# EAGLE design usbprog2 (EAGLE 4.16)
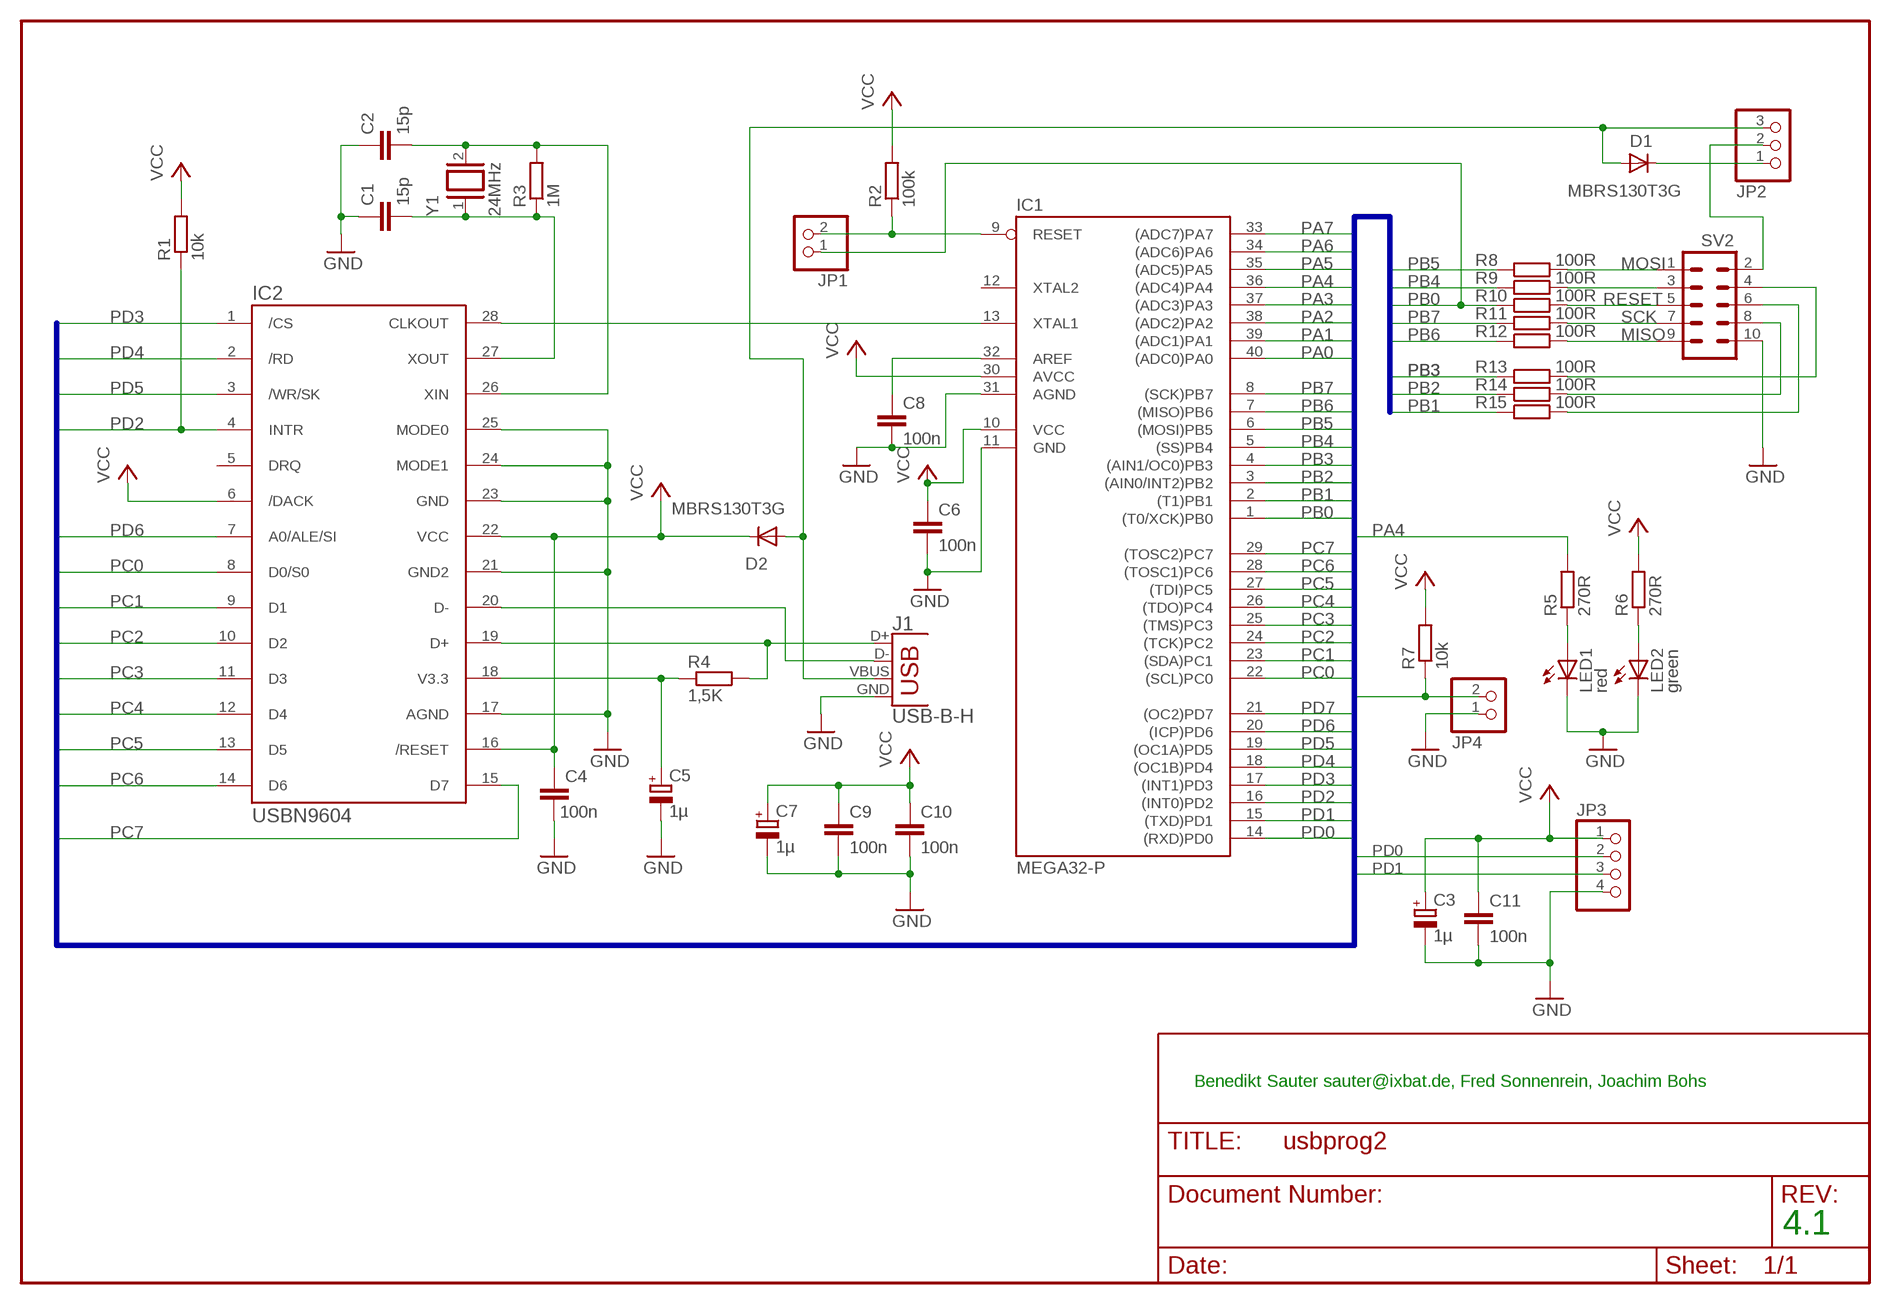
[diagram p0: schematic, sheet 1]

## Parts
C1  15p  C-EU025-024X044  [C025-024X044]
C2  15p  C-EU025-024X044  [C025-024X044]
C3  1µ  CPOL-EUE2-5  [E2-5]
C4  100n  C-EU050-024X044  [C050-024X044]
C5  1µ  CPOL-EUE2-5  [E2-5]
C6  100n  C-EU050-024X044  [C050-024X044]
C7  1µ  CPOL-EUE2-5  [E2-5]
C8  100n  C-EU050-024X044  [C050-024X044]
C9  100n  C-EU050-024X044  [C050-024X044]
C10  100n  C-EU050-024X044  [C050-024X044]
C11  100n  C-EU050-024X044  [C050-024X044]
D1  MBRS130T3G  DIODE-DO35-10  [DO35-10]
D2  MBRS130T3G  DIODE-DO35-10  [DO35-10]
IC1  MEGA32-P  [DIL40]
IC2  USBN9604  [SO28-3]
J1  USB-B-H  [USB-B-H]
JP1  PINHD-1X2  [1X02]
JP2  PINHD-1X3  [1X03]
JP3  PINHD-1X4  [1X04]
JP4  PINHD-1X2  [1X02]
LED1  red  LED3MM  [LED3MM]
LED2  green  LED3MM  [LED3MM]
R1  10k  R-EU_0207/10  [0207/10]
R2  100k  R-EU_0207/10  [0207/10]
R3  1M  R-EU_0207/10  [0207/10]
R4  1,5K  R-EU_0207/10  [0207/10]
R5  270R  R-EU_0207/10  [0207/10]
R6  270R  R-EU_0207/12  [0207/12]
R7  10k  R-EU_0207/10  [0207/10]
R8  100R  R-EU_0207/12  [0207/12]
R9  100R  R-EU_0207/12  [0207/12]
R10  100R  R-EU_0207/12  [0207/12]
R11  100R  R-EU_0207/12  [0207/12]
R12  100R  R-EU_0207/12  [0207/12]
R13  100R  R-EU_0207/12  [0207/12]
R14  100R  R-EU_0207/12  [0207/12]
R15  100R  R-EU_0207/12  [0207/12]
SV2  ML10L  [ML10L]
Y1  24MHz  XTAL/S  [QS]

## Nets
GND: C1.1 C2.1 C3.- C4.2 C5.- C6.2 C7.- C8.2 C9.2 C10.2 C11.2 IC1.11(GND) IC1.31(AGND) IC2.17(AGND) IC2.21(GND2) IC2.23(GND) IC2.24(MODE1) IC2.25(MODE0) J1.GND JP3.4 JP4.1 LED1.K(C) LED2.K(C) SV2.10
N$1: D1.A D2.A J1.VBUS JP2.3
N$2: JP2.2 SV2.2
N$3: D1.C JP2.1
N$4: IC1.13(XTAL1) IC2.28(CLKOUT)
N$5: R14.2 SV2.8
N$6: C8.1 IC1.32(AREF)
N$7: C5.+ IC2.18(V3.3) R4.1
N$8: C2.2 IC2.26(XIN) R3.2 Y1.2
N$9: LED1.A R5.1
N$10: LED2.A R6.1
N$11: C1.2 IC2.27(XOUT) R3.1 Y1.1
N$12: IC2.19(D+) J1.D+ R4.2
N$13: R15.2 SV2.6
N$14: R13.2 SV2.4
N$15: IC2.20(D-) J1.D-
N$16: R12.2 SV2.9
N$17: R11.2 SV2.7
N$18: R10.2 SV2.5
N$19: R9.2 SV2.3
N$20: R8.2 SV2.1
PA0: IC1.40((ADC0)PA0)
PA1: IC1.39((ADC1)PA1)
PA2: IC1.38((ADC2)PA2)
PA3: IC1.37((ADC3)PA3)
PA4: IC1.36((ADC4)PA4) R5.2
PA5: IC1.35((ADC5)PA5)
PA6: IC1.34((ADC6)PA6)
PA7: IC1.33((ADC7)PA7) JP4.2 R7.1
PB0: IC1.1((T0/XCK)PB0) JP1.1 R10.1
PB1: IC1.2((T1)PB1) R15.1
PB2: IC1.3((AIN0/INT2)PB2) R14.1
PB3: IC1.4((AIN1/OC0)PB3) R13.1
PB4: IC1.5((SS)PB4) R9.1
PB5: IC1.6((MOSI)PB5) R8.1
PB6: IC1.7((MISO)PB6) R12.1
PB7: IC1.8((SCK)PB7) R11.1
PC0: IC1.22((SCL)PC0) IC2.8(D0/S0)
PC1: IC1.23((SDA)PC1) IC2.9(D1)
PC2: IC1.24((TCK)PC2) IC2.10(D2)
PC3: IC1.25((TMS)PC3) IC2.11(D3)
PC4: IC1.26((TDO)PC4) IC2.12(D4)
PC5: IC1.27((TDI)PC5) IC2.13(D5)
PC6: IC1.28((TOSC1)PC6) IC2.14(D6)
PC7: IC1.29((TOSC2)PC7) IC2.15(D7)
PD0: IC1.14((RXD)PD0) JP3.2
PD1: IC1.15((TXD)PD1) JP3.3
PD2: IC1.16((INT0)PD2) IC2.4(INTR) R1.1
PD3: IC1.17((INT1)PD3) IC2.1(/CS)
PD4: IC1.18((OC1B)PD4) IC2.2(/RD)
PD5: IC1.19((OC1A)PD5) IC2.3(/WR/SK)
PD6: IC1.20((ICP)PD6) IC2.7(A0/ALE/SI)
PD7: IC1.21((OC2)PD7)
RESET: IC1.9(RESET) JP1.2 R2.1
VCC: C3.+ C4.1 C6.1 C7.+ C9.1 C10.1 C11.1 D2.C IC1.10(VCC) IC1.30(AVCC) IC2.6(/DACK) IC2.16(/RESET) IC2.22(VCC) JP3.1 R1.2 R2.2 R6.2 R7.2
Unconnected: IC1.12(XTAL2) IC2.5(DRQ)

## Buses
PD0,PD1,PD2,PD3,PD4,PD5,PD6,PD7,PC0,PC1,PC2,PC3,PC4,PC5,PC6,PC7,PB0,PB1,PB2,PB3,PB4,PB5,PB6,PB7,PA0,PA1,PA2,PA3,PA4,PA5,PA6,PA7

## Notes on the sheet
- MOSI
- PB4
- RESET
- SCK
- MISO
- PB3 | PB3
- PB2
- PB1
- Benedikt Sauter sauter@ixbat.de, Fred Sonnenrein, Joachim Bohs
- 4.1

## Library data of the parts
C1 C2 C4 C6 C8-C11 = rcl:C-EU: CAPACITOR, European symbol
C3 C5 C7 = rcl:CPOL-EU: POLARIZED CAPACITOR, European symbol
D1 D2 = diode:DIODE-: DIODE
IC1 = atmel:MEGA32-P: MICROCONTROLLER 32 Kbytes FLASH 2 Kbytes SRAM 1 Kbytes EEPROM USART 8-channel 10 bit ADC Source: www.atmel.com .. doc2503.pdf
IC2 = bene:USBN9604
J1 = con-usb:USB: USB Connectors
JP1 JP4 = pinhead:PINHD-1X2: PIN HEADER
JP2 = pinhead:PINHD-1X3: PIN HEADER
JP3 = pinhead:PINHD-1X4: PIN HEADER
LED1 LED2 = led:LED: LED
R1-R15 = rcl:R-EU_: RESISTOR, European symbol
SV2 = con-harting-ml:ML10: HARTING
Y1 = special:XTAL/S: CRYSTAL

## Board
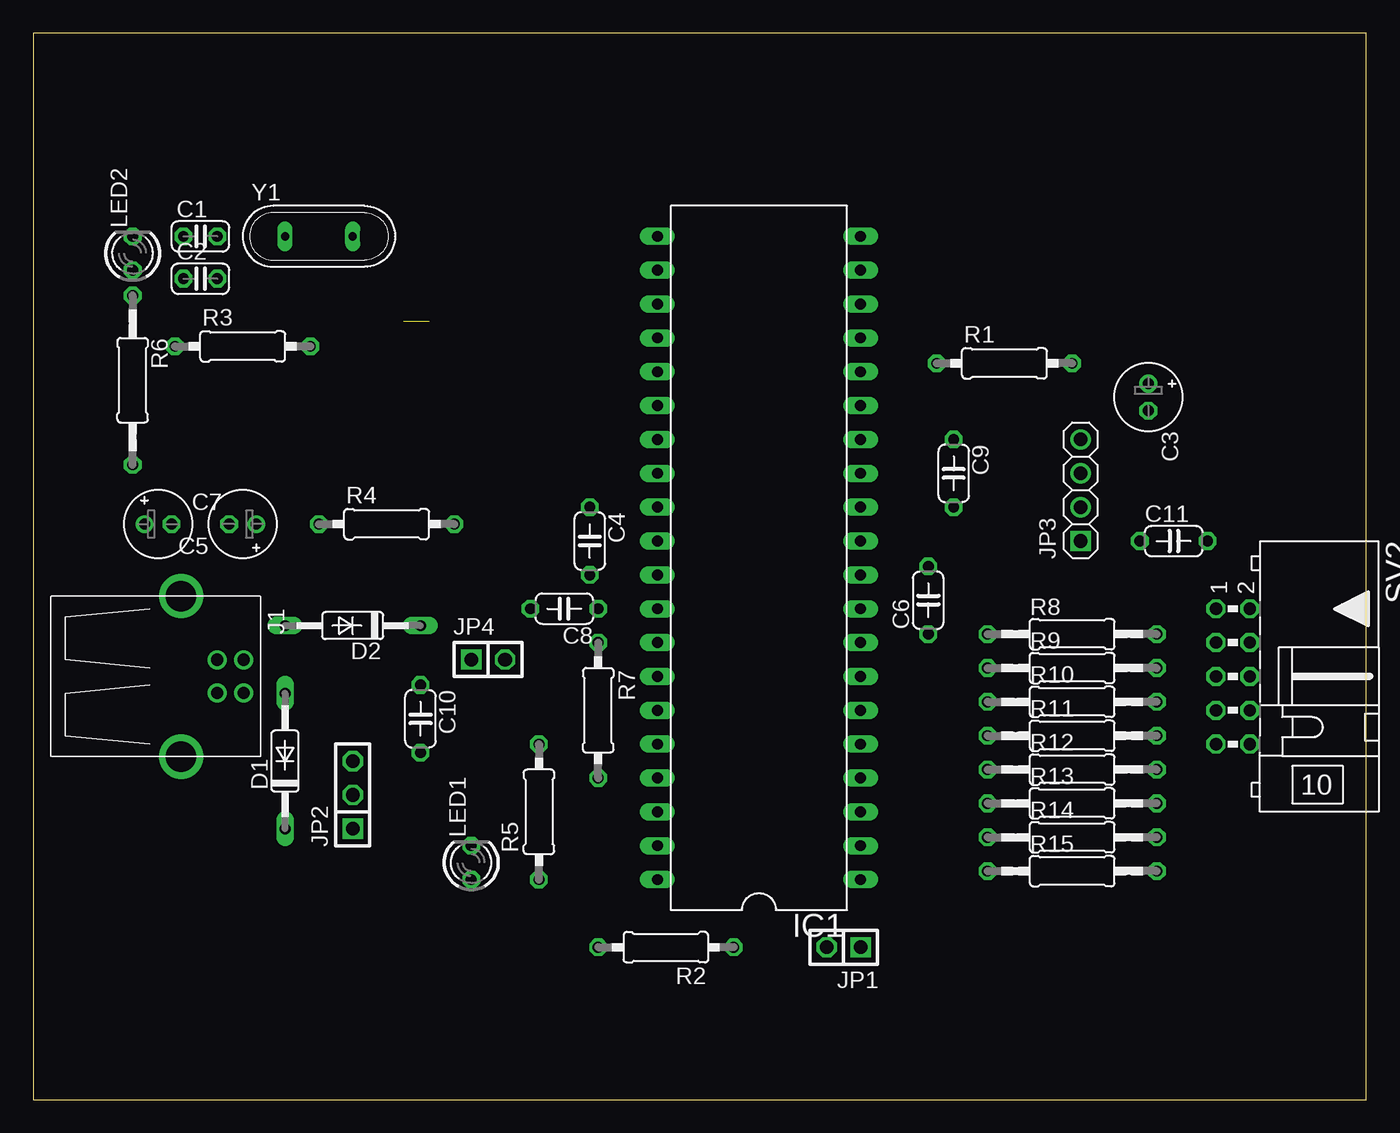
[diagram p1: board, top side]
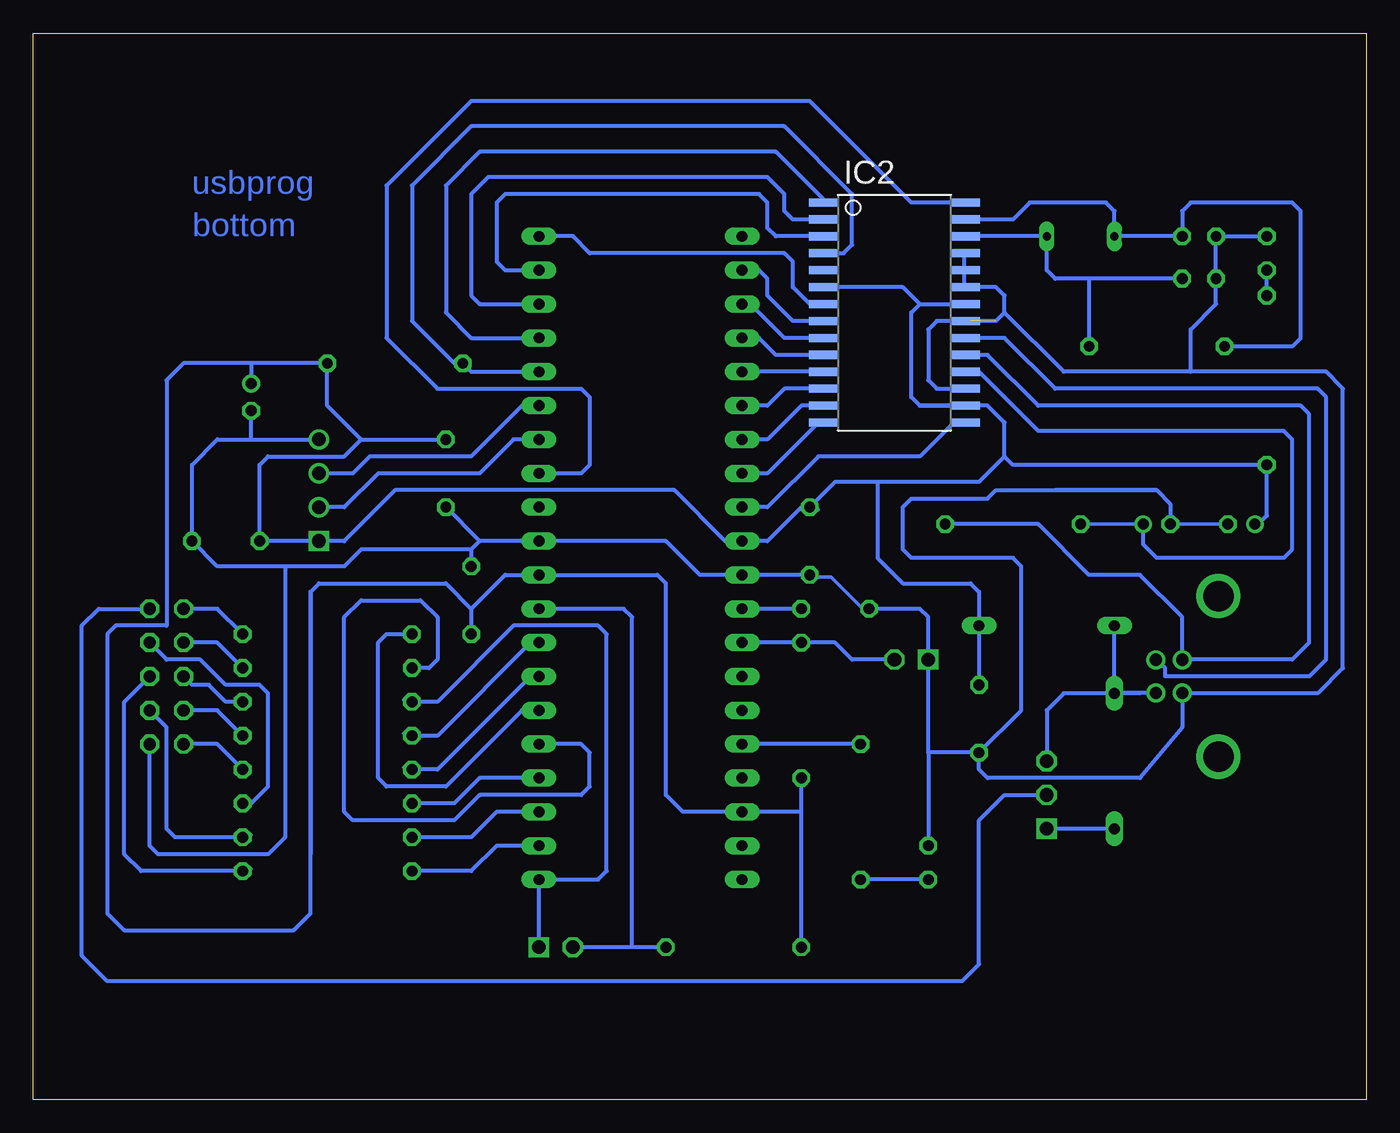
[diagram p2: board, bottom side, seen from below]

Size 100 x 80 mm. Coordinates in mm from the lower left corner, seen from the top.
Outline: 0,0 100,0 100,80 0,80 0,0
Copper layers (1*16): Top 0.035mm / dielectric 1.5mm / Bottom 0.035mm
Design rules "default": minimum track width 10mil, minimum drill 24mil, track to track 8mil, track to pad 8mil, pad to pad 8mil, via to via 8mil, smd to smd 8mil, copper to edge 40mil, drill to drill 8mil, minimum pad ring 10mil, minimum via ring 8mil, stop-mask expansion 4mil, vias tented up to drill 0mil, thermal gap 10mil

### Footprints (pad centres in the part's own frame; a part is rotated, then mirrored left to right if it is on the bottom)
C025-024X044 = drill 0.813 octagon: 1 -1.27,0; 2 1.27,0
E2-5 = drill 0.813 pad 1.27 round: + -1.016,0 | drill 0.813 pad 1.27 octagon: - 1.016,0
C050-024X044 = drill 0.813 octagon: 1 -2.54,0; 2 2.54,0
DO35-10 = drill 0.813 long: A 5.08,0; C -5.08,0
DIL40 = drill 0.813 long: 1 -24.13,-7.62; 2 -21.59,-7.62; 3 -19.05,-7.62; 4 -16.51,-7.62; 5 -13.97,-7.62; 6 -11.43,-7.62; 7 -8.89,-7.62; 8 -6.35,-7.62; 9 -3.81,-7.62; 10 -1.27,-7.62; 11 1.27,-7.62; 12 3.81,-7.62; 13 6.35,-7.62; 14 8.89,-7.62; 15 11.43,-7.62; 16 13.97,-7.62; 17 16.51,-7.62; 18 19.05,-7.62; 19 21.59,-7.62; 20 24.13,-7.62; 21 24.13,7.62; 22 21.59,7.62; 23 19.05,7.62; 24 16.51,7.62; 25 13.97,7.62; 26 11.43,7.62; 27 8.89,7.62; 28 6.35,7.62; 29 3.81,7.62; 30 1.27,7.62; 31 -1.27,7.62; 32 -3.81,7.62; 33 -6.35,7.62; 34 -8.89,7.62; 35 -11.43,7.62; 36 -13.97,7.62; 37 -16.51,7.62; 38 -19.05,7.62; 39 -21.59,7.62; 40 -24.13,7.62
SO28-3 = smd 0.61 x 2.21: 1 -8.255,-5.315; 2 -6.985,-5.315; 3 -5.715,-5.315; 4 -4.445,-5.315; 5 -3.175,-5.315; 6 -1.905,-5.315; 7 -0.635,-5.315; 8 0.635,-5.315; 9 1.905,-5.315; 10 3.175,-5.315; 11 4.445,-5.315; 12 5.715,-5.315; 13 6.985,-5.315; 14 8.255,-5.315; 15 8.255,5.315; 16 6.985,5.315; 17 5.715,5.315; 18 4.445,5.315; 19 3.175,5.315; 20 1.905,5.315; 21 0.635,5.315; 22 -0.635,5.315; 23 -1.905,5.315; 24 -3.175,5.315; 25 -4.445,5.315; 26 -5.715,5.315; 27 -6.985,5.315; 28 -8.255,5.315
USB-B-H = drill 0.914 round: D+ 0,1.25; D- 1.981,1.25; GND 0,-1.25; VBUS 1.981,-1.25 | drill 2.286 round: P$1 -2.718,-6.02; P$2 -2.718,6.02
1X02 = drill 1.016 square: 1 -1.27,0 | drill 1.016 octagon: 2 1.27,0
1X03 = drill 1.016 square: 1 -2.54,0 | drill 1.016 octagon: 2 0,0; 3 2.54,0
1X04 = drill 1.016 square: 1 -3.81,0 | drill 1.016 round: 2 -1.27,0; 3 1.27,0; 4 3.81,0
LED3MM = drill 0.813 octagon: A -1.27,0; K 1.27,0
0207/10 = drill 0.813 octagon: 1 -5.08,0; 2 5.08,0
0207/12 = drill 0.813 octagon: 1 -6.35,0; 2 6.35,0
ML10L = drill 0.914 octagon: 1 -5.08,-1.27; 2 -5.08,1.27; 3 -2.54,-1.27; 4 -2.54,1.27; 5 0,-1.27; 6 0,1.27; 7 2.54,-1.27; 8 2.54,1.27; 9 5.08,-1.27; 10 5.08,1.27
QS = drill 0.61 long: 1 -2.54,0; 2 2.54,0

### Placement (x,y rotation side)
C1  12.54,64.77 0 top
C2  12.54,61.59 0 top
C3  83.66,52.7 270 top
C4  41.74,41.91 270 top
C5  15.71,43.18 180 top
C6  67.14,37.46 90 top
C7  9.36,43.18 0 top
C8  39.84,36.83 180 top
C9  69.05,46.98 270 top
C10  29.04,28.57 270 top
C11  85.56,41.91 0 top
D1  18.88,25.39 90 top
D2  23.96,35.55 180 top
IC1  54.45,40.64 90 top
IC2  35.39,59.05 270 bottom
J1  13.81,31.74 0 top
JP1  60.8,11.43 180 top
JP2  23.96,22.86 90 top
JP3  78.58,45.72 90 top
JP4  34.12,33.02 0 top
LED1  32.85,17.77 90 top
LED2  7.46,63.5 90 top
R1  72.86,55.24 0 top
R2  47.46,11.43 180 top
R3  15.71,56.51 0 top
R4  26.5,43.18 0 top
R5  37.94,21.58 90 top
R6  7.46,53.97 270 top
R7  42.38,29.2 270 top
R8  77.94,34.92 0 top
R9  77.94,32.38 0 top
R10  77.94,29.84 0 top
R11  77.94,27.3 0 top
R12  77.94,24.76 0 top
R13  77.94,22.22 0 top
R14  77.94,19.68 0 top
R15  77.94,17.14 0 top
SV2  90,31.74 270 top
Y1  21.42,64.77 0 top

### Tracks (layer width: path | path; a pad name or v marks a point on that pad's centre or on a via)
GND  (1 unrouted)
  Bottom 0.254: IC2.23 30.16,61.11 | 30.16,62.07 IC2.24 | C5.- C7.- | C8.2 37.94,36.98 40.16,39.21 41.11,39.21 C4.2
  Bottom 0.305: 66.51,41.91 IC1.11 52.54,41.91 50,39.37 IC1.31 C4.2 | 67.14,41.27 C6.2 | 83.66,49.53 86.19,49.53 88.1,47.62 C11.2 86.19,40 81.11,40 | 83.66,49.53 JP3.4 | 66.51,41.91 C9.2 | 66.51,41.91 67.14,41.27 | 67.14,41.27 75.4,41.27 76.67,40 81.11,40 | 83.66,49.53 C3.- | 81.11,40 81.11,19.68 82.39,18.41 90.64,18.41 91.28,19.04 SV2.10 | IC2.17 32.22,53.34 32.85,53.97 32.85,57.78 32.22,58.41 27.77,58.41 27.14,59.05 | IC2.21 29.68,58.41 | 27.14,59.05 27.14,60.32 27.77,60.96 IC2.23 30.31,60.96 30.16,61.11 | IC2.25 30.31,63.5 30.16,63.34 30.16,62.07 | 30.16,61.11 30.16,62.07 | 30.16,61.11 30.16,62.07 | LED2.K C1.1 C2.1 11.27,59.69 13.17,57.78 13.17,54.61 | 13.17,54.61 22.7,54.61 27.14,59.05 | C8.2 33.49,36.83 32.85,36.19 JP4.1 32.85,26.03 | 15.71,45.72 23.33,45.72 | C5.- 14.69,44.7 15.71,45.72 | 15.71,45.72 27.77,45.72 28.41,45.08 34.12,45.08 34.76,44.45 34.76,41.27 34.12,40.64 26.5,40.64 25.87,40 25.87,29.2 C10.2 | 32.85,26.03 LED1.K | C10.2 29.04,24.76 28.41,24.12 16.98,24.12 13.81,27.93 13.81,30.47 | C10.2 32.85,26.03 | 13.81,30.47 J1.GND | 13.81,30.47 3.64,30.47 1.74,32.38 1.74,53.34 3.01,54.61 13.17,54.61
N$1
  Bottom 0.305: J1.VBUS 16.98,30.49 | 16.98,30.49 18.23,30.49 | 16.98,30.49 16.98,30.47 D1.A | D1.A D2.A | D1.A 22.7,30.47 23.96,29.2 JP2.3
N$2
  Bottom 0.305: SV2.2 95.08,36.83 96.36,35.55 96.36,10.79 94.45,8.89 30.31,8.89 29.04,10.16 29.04,20.95 27.14,22.86 JP2.2
N$3
  Bottom 0.305: D1.C JP2.1
N$4
  Bottom 0.305: IC1.13 58.89,46.98 58.25,47.62 58.25,52.7 58.89,53.34 69.69,53.34 73.5,57.15 73.5,68.57 67.14,74.92 41.74,74.92 34.12,67.3 IC2.28 29.68,67.3
N$5
  Bottom 0.254: 83.66,19.84 R14.2
  Bottom 0.305: R14.2 89.37,19.68 90,20.31 90,27.93 SV2.8
N$6
  Bottom 0.305: C8.1 IC1.32
N$7
  Bottom 0.254: C5.+ R4.1
  Bottom 0.305: IC2.18 29.04,54.61 24.6,50.16 6.18,50.16 5.55,49.53 5.55,41.27 6.18,40.64 15.71,40.64 16.73,41.65 C5.+
N$8
  Bottom 0.305: IC2.26 Y1.2 23.96,62.23 23.33,61.59 20.79,61.59 | C2.2 20.79,61.59 | 20.79,61.59 R3.2
N$9
  Bottom 0.305: LED1.A R5.1
N$10
  Bottom 0.305: R6.1 LED2.A
N$11
  Bottom 0.305: IC2.27 26.5,66.03 25.23,67.3 19.52,67.3 18.88,66.67 Y1.1 C1.2 13.81,66.67 13.17,67.3 5.55,67.3 4.92,66.67 4.92,57.15 5.55,56.51 R3.1
N$12
  Bottom 0.305: IC2.19 28.41,55.88 24.6,52.07 4.92,52.07 4.28,51.43 4.28,34.29 5.55,33.02 13.81,33.02 | R4.2 24.6,43.18 20.79,39.37 16.98,39.37 13.81,36.19 13.81,33.02 | 13.81,33.02 J1.D+
N$13
  Bottom 0.254: 83.66,17.3 R15.2
  Bottom 0.305: R15.2 91.91,17.14 93.18,18.41 93.18,29.84 SV2.6
N$14
  Bottom 0.305: R13.2 83.66,22.22 82.39,23.49 82.39,30.47 83.02,31.11 85.56,31.11 87.47,33.02 90,33.02 SV2.4
N$15
  Bottom 0.305: IC2.20 27.14,57.15 23.33,53.34 3.64,53.34 3.01,52.7 3.01,33.02 4.28,31.74 15.08,31.74 15.08,32.38 15.71,33.02 15.73,33 J1.D-
N$16
  Bottom 0.305: R12.2 86.19,26.66 SV2.9
N$17
  Bottom 0.305: R11.2 86.19,29.2 SV2.7
N$18
  Bottom 0.305: R10.2 85.56,29.84 86.83,31.11 88.1,31.11 SV2.5
N$19
  Bottom 0.305: R9.2 86.19,34.29 SV2.3
N$20
  Bottom 0.305: R8.2 86.19,36.83 SV2.1
PA4
  Bottom 0.305: R5.2 IC1.36
PA7
  Bottom 0.305: IC1.33 R7.1 39.84,34.29 38.57,33.02 JP4.2
PB0
  Bottom 0.254: R10.1 72.22,30
  Bottom 0.305: R10.1 69.69,29.84 63.97,35.55 57.62,35.55 56.98,34.92 56.98,17.14 57.62,16.5 IC1.1 JP1.1
PB1
  Bottom 0.305: IC1.2 65.24,19.04 67.14,17.14 R15.1
PB2
  Bottom 0.305: IC1.3 65.24,21.58 67.14,19.68 R14.1
PB3
  Bottom 0.305: IC1.4 66.51,24.12 68.41,22.22 R13.1
PB4
  Bottom 0.305: IC1.5 58.89,26.66 58.25,26.03 58.25,23.49 58.89,22.86 66.51,22.86 68.41,20.95 76.03,20.95 76.67,21.58 76.67,36.19 75.4,37.46 70.95,37.46 69.69,36.19 69.69,33.02 70.32,32.38 R9.1
PB5
  Bottom 0.305: IC1.6 63.34,29.2 69.05,23.49 73.5,23.49 74.13,24.12 74.13,34.29 73.5,34.92 R8.1
PB6
  Bottom 0.254: R12.1 72.22,24.92
  Bottom 0.305: IC1.7 62.7,31.74 69.69,24.76 R12.1
PB7
  Bottom 0.254: R11.1 72.22,27.46
  Bottom 0.305: IC1.8 62.7,34.29 69.69,27.3 R11.1
PC0
  Bottom 0.305: IC2.8 43.02,58.41 44.92,60.32 44.92,61.59 45.55,62.23 IC1.22
PC1
  Bottom 0.305: IC2.9 43.65,57.15 46.19,59.69 IC1.23
PC2
  Bottom 0.305: IC2.10 44.28,55.88 45.55,57.15 IC1.24
PC3
  Bottom 0.305: IC2.11 IC1.25
PC4
  Bottom 0.305: IC2.12 43.65,53.34 44.92,52.07 IC1.26
PC5
  Bottom 0.305: IC2.13 42.38,52.07 44.92,49.53 IC1.27
PC6
  Bottom 0.305: IC2.14 41.11,50.8 44.92,46.98 IC1.28
PC7
  Bottom 0.305: IC1.29 44.92,44.45 41.11,48.26 33.49,48.26 30.95,50.8 IC2.15
PD0
  Bottom 0.305: IC1.14 63.97,49.53 66.51,46.98 74.13,46.98 76.67,44.45 JP3.2
PD1
  Bottom 0.305: IC1.15 63.34,52.07 67.14,48.26 74.77,48.26 76.03,46.98 JP3.3
PD2
  Bottom 0.305: IC1.16 67.14,54.61 R1.1 68.41,55.24 71.59,58.41 71.59,68.57 67.14,73.02 43.65,73.02 38.57,67.94 38.57,64.13 39.2,63.5 IC2.4 41.11,63.5
PD3
  Bottom 0.305: IC1.17 67.14,57.15 69.05,59.05 69.05,68.57 66.51,71.11 44.28,71.11 40.48,67.3 IC2.1 41.11,67.3
PD4
  Bottom 0.305: IC1.18 66.51,59.69 67.14,60.32 67.14,67.94 65.88,69.21 44.92,69.21 43.65,67.94 43.65,66.67 43.02,66.03 IC2.2 40.48,66.03
PD5
  Bottom 0.305: IC1.19 64.61,62.23 65.24,62.86 65.24,67.3 64.61,67.94 45.55,67.94 44.92,67.3 44.92,65.4 44.28,64.77 IC2.3
PD6
  Bottom 0.305: IC2.7 41.74,59.69 43.02,60.96 43.02,62.86 43.65,63.5 58.25,63.5 59.52,64.77 IC1.20
RESET
  Bottom 0.305: R2.1 55.08,11.43 | 55.08,11.43 JP1.2 | 55.08,11.43 55.08,36.19 55.71,36.83 IC1.9
VCC
  Bottom 0.254: C4.1 41.11,44.29
  Bottom 0.305: 75.4,49.53 C9.1 | 75.4,49.53 76.67,48.26 82.39,48.26 83.02,47.62 C11.1 JP3.1 76.67,41.91 72.86,45.72 51.91,45.72 48.09,41.91 IC1.30 44.92,41.91 42.38,44.45 C4.1 39.84,46.35 36.66,46.35 | 67.14,36.83 C6.1 | 67.14,36.83 64.61,39.37 IC1.10 53.17,39.37 52.54,38.73 52.54,22.86 51.27,21.58 42.38,21.58 | 67.14,36.83 69.05,38.73 78.58,38.73 79.21,38.1 | 94.45,34.92 94.45,18.41 | 79.21,38.1 79.21,18.41 | 79.21,38.1 79.21,13.97 80.48,12.7 93.18,12.7 94.45,13.97 94.45,34.92 | 94.45,34.92 93.81,35.55 90,35.55 90,53.97 88.73,55.24 83.66,55.24 | 83.66,55.24 R1.2 77.94,52.07 75.4,49.53 | 83.66,55.24 C3.+ | R2.2 42.38,21.58 | 42.38,21.58 R7.2 | 33.49,52.07 IC2.16 | 33.49,52.07 34.12,52.7 34.12,59.05 33.49,59.69 | 29.68,59.69 IC2.22 33.49,59.69 | IC2.6 34.76,60.96 33.49,59.69 | 33.49,52.07 28.41,52.07 27.14,50.8 27.14,48.26 | 27.14,48.26 29.04,46.35 36.66,46.35 | C7.+ 8.09,43.18 7.46,43.81 R6.2 26.5,47.62 27.14,48.26 | C10.1 D2.C 29.04,38.1 29.68,38.73 34.76,38.73 36.66,40.64 36.66,46.35

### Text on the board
Bottom: usbprog | bottom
